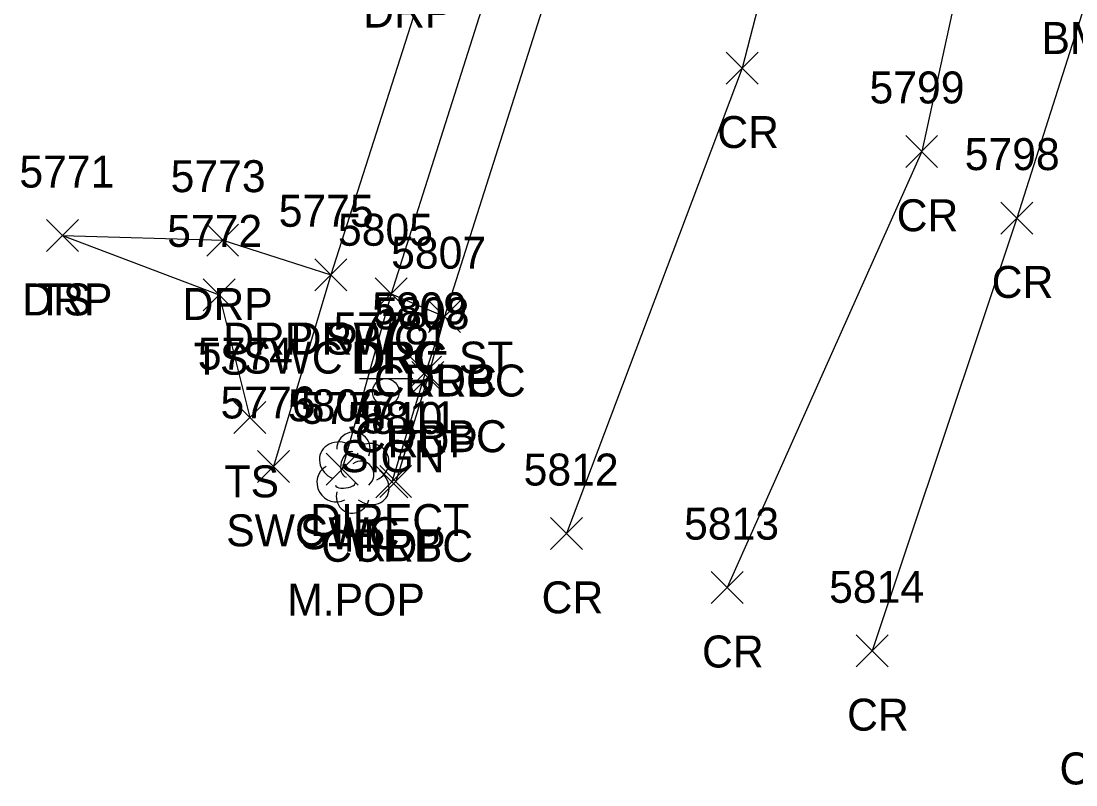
# Model space of a CAD drawing. Extents: x 1462089 to 1464015, y 730534 to 736144.
# Drawn here: x 1462304.3 to 1462370.3, y 730545.4 to 730593.2 of the extents above; entities that cross this region are included whole.
import ezdxf

# ---------------------------------------------------------------- set-up
doc = ezdxf.new("R2010")
doc.units = 0
for name, color, linetype in [('C_C', 7, 'Continuous'), ('L_A', 7, 'Continuous'), ('L_C', 7, 'Continuous'), ('L_I', 7, 'Continuous'), ('L_TIC', 7, 'Continuous'), ('LELB', 7, 'Continuous'), ('LTD', 7, 'Continuous'), ('P_A', 7, 'Continuous'), ('P_I', 7, 'Continuous'), ('P_TIC', 7, 'Continuous'), ('PET', 7, 'Continuous'), ('PRC', 7, 'Continuous'), ('R_A', 7, 'Continuous'), ('R_I', 7, 'Continuous'), ('R_TIC', 7, 'Continuous'), ('RC', 7, 'Continuous'), ('RDP', 7, 'Continuous'), ('RSW', 7, 'Continuous'), ('S_A', 7, 'Continuous'), ('S_C', 7, 'Continuous'), ('S_I', 7, 'Continuous'), ('SSGN', 7, 'Continuous')]:
    doc.layers.add(name, color=color, linetype=linetype)

msp = doc.modelspace()

# ---------------------------------------------------------------- linework, layer by layer
at = {"layer": 'L_TIC'}
for points in [[(1462305.867, 730578.733), (1462307.867, 730580.733)], [(1462307.867, 730578.733), (1462305.867, 730580.733)], [(1462315.69, 730575.023), (1462317.69, 730577.023)], [(1462317.69, 730575.023), (1462315.69, 730577.023)], [(1462317.609, 730567.347), (1462319.609, 730569.347)], [(1462319.609, 730567.347), (1462317.609, 730569.347)]]:
    msp.add_lwpolyline(points, dxfattribs=at)
at = {"layer": 'LELB'}
msp.add_lwpolyline([(1462306.867, 730579.733), (1462316.69, 730576.023), (1462318.609, 730568.347)], dxfattribs=at)
at = {"layer": 'LTD'}
msp.add_line((1462325.05, 730564.948), (1462325.05, 730564.948), dxfattribs=at)
msp.add_line((1462325.05, 730564.948), (1462325.05, 730564.948), dxfattribs=at)
msp.add_arc((1462325.096, 730566.382), 1.047, 335.52715, 180.95627, dxfattribs=at)
for centre, major_axis, ratio, start_param, end_param in [((1462324.258, 730565.615), (1.21, -0.512), 0.895232, 1.570796, 4.712389), ((1462326.091, 730565.532), (-1.141, -0.483), 0.949671, 1.570796, 4.712389), ((1462324.841, 730565.407), (-0.208, -0.792), 0.645439, 3.141593, 6.283185), ((1462325.55, 730564.782), (-0.5, 0.667), 0.989748, 3.141593, 6.283185), ((1462323.967, 730564.24), (0.584, -1.042), 0.959034, 3.141593, 6.283185), ((1462326.05, 730564.115), (-1.09, 0.792), 0.841452, 1.570796, 4.712389), ((1462325.05, 730563.448), (0.265, 1.061), 0.942809, 1.570796, 4.712389), ((1462324.592, 730564.198), (-0.625, -0.083), 0.423636, 0, 3.141593)]:
    msp.add_ellipse(centre, major_axis=major_axis, ratio=ratio, start_param=start_param, end_param=end_param, dxfattribs=at)
at = {"layer": 'P_TIC'}
for points in [[(1462348.446, 730589.208), (1462350.446, 730591.208)], [(1462350.446, 730589.208), (1462348.446, 730591.208)], [(1462359.68, 730584), (1462361.68, 730586)], [(1462361.68, 730584), (1462359.68, 730586)], [(1462365.634, 730579.828), (1462367.634, 730581.828)], [(1462367.634, 730579.828), (1462365.634, 730581.828)], [(1462329.793, 730573.658), (1462331.793, 730575.658)], [(1462331.793, 730573.658), (1462329.793, 730575.658)], [(1462328.749, 730569.858), (1462330.749, 730571.858)], [(1462330.749, 730569.858), (1462328.749, 730571.858)], [(1462326.74, 730563.348), (1462328.74, 730565.348)], [(1462328.74, 730563.348), (1462326.74, 730565.348)], [(1462337.444, 730560.087), (1462339.444, 730562.087)], [(1462339.444, 730560.087), (1462337.444, 730562.087)], [(1462347.492, 730556.7), (1462349.492, 730558.7)], [(1462349.492, 730556.7), (1462347.492, 730558.7)], [(1462356.577, 730552.747), (1462358.577, 730554.747)], [(1462358.577, 730552.747), (1462356.577, 730554.747)]]:
    msp.add_lwpolyline(points, dxfattribs=at)
at = {"layer": 'PET'}
msp.add_lwpolyline([(1462369.308, 730697.926), (1462368.209, 730694.185), (1462362.156, 730675.48), (1462361.372, 730672.287), (1462352.142, 730642.733), (1462339.819, 730603.063), (1462338.492, 730598.895), (1462330.793, 730574.658), (1462329.749, 730570.858), (1462327.74, 730564.348)], dxfattribs=at)
at = {"layer": 'PRC'}
for points in [[(1462502.241, 731140.649), (1462491.591, 731093.412), (1462481.409, 731051.886), (1462466.381, 730998.853), (1462449.742, 730941.326), (1462438.111, 730890.414), (1462425.454, 730844.203), (1462414.378, 730806.637), (1462401.133, 730755.946), (1462392.12, 730727.265), (1462378.758, 730682.128), (1462374.561, 730668.664), (1462358.3, 730624.573), (1462349.446, 730590.208), (1462338.444, 730561.087)], [(1462522.114, 731136.266), (1462509.014, 731086.504), (1462495.843, 731048.676), (1462480.832, 730995.433), (1462460.794, 730938.782), (1462449.007, 730886.807), (1462435.474, 730841.095), (1462424.603, 730802.226), (1462409.981, 730750.745), (1462401.876, 730724.374), (1462388.003, 730678.771), (1462384.493, 730666.354), (1462369.098, 730623.58), (1462360.68, 730585), (1462348.492, 730557.7)], [(1462531.515, 731132.984), (1462517.28, 731085.282), (1462509.353, 731045.029), (1462493.599, 730992.368), (1462476.953, 730933.085), (1462462.375, 730883.835), (1462447.905, 730837.268), (1462435.369, 730797.923), (1462416.948, 730748.336), (1462410.801, 730719.379), (1462396.341, 730673.49), (1462394.762, 730664.922), (1462379.239, 730620.511), (1462379.284, 730620.518), (1462366.634, 730580.828), (1462357.577, 730553.747)]]:
    msp.add_lwpolyline(points, dxfattribs=at)
at = {"layer": 'R_TIC'}
for points in [[(1462305.867, 730578.733), (1462307.867, 730580.733)], [(1462307.867, 730578.733), (1462305.867, 730580.733)], [(1462315.905, 730578.447), (1462317.905, 730580.447)], [(1462317.905, 730578.447), (1462315.905, 730580.447)], [(1462322.672, 730576.282), (1462324.672, 730578.282)], [(1462324.672, 730576.282), (1462322.672, 730578.282)], [(1462322.672, 730576.282), (1462324.672, 730578.282)], [(1462324.672, 730576.282), (1462322.672, 730578.282)], [(1462326.462, 730575.094), (1462328.462, 730577.094)], [(1462328.462, 730575.094), (1462326.462, 730577.094)], [(1462326.462, 730575.094), (1462328.462, 730577.094)], [(1462328.462, 730575.094), (1462326.462, 730577.094)], [(1462329.793, 730573.658), (1462331.793, 730575.658)], [(1462331.793, 730573.658), (1462329.793, 730575.658)], [(1462329.793, 730573.658), (1462331.793, 730575.658)], [(1462331.793, 730573.658), (1462329.793, 730575.658)], [(1462328.606, 730570.173), (1462330.606, 730572.173)], [(1462330.606, 730570.173), (1462328.606, 730572.173)], [(1462319.084, 730564.284), (1462321.084, 730566.284)], [(1462321.084, 730564.284), (1462319.084, 730566.284)], [(1462323.382, 730564.104), (1462325.382, 730566.104)], [(1462325.382, 730564.104), (1462323.382, 730566.104)], [(1462326.499, 730563.316), (1462328.499, 730565.316)], [(1462328.499, 730563.316), (1462326.499, 730565.316)]]:
    msp.add_lwpolyline(points, dxfattribs=at)
at = {"layer": 'RC'}
msp.add_lwpolyline([(1462330.793, 730574.658), (1462329.606, 730571.173), (1462327.499, 730564.316)], dxfattribs=at)
at = {"layer": 'RDP'}
for points in [[(1462306.867, 730579.733), (1462316.905, 730579.447), (1462323.672, 730577.282)], [(1462327.462, 730576.094), (1462330.793, 730574.658)]]:
    msp.add_lwpolyline(points, dxfattribs=at)
at = {"layer": 'RSW'}
for points in [[(1462360.519, 730693.816), (1462356.442, 730681.408), (1462355.857, 730679.16), (1462349.665, 730659.971), (1462348.127, 730654.542), (1462330.678, 730599.137), (1462323.672, 730577.282), (1462320.084, 730565.284)], [(1462348.724, 730643.964), (1462334.507, 730598.298), (1462327.462, 730576.094), (1462324.382, 730565.104)]]:
    msp.add_lwpolyline(points, dxfattribs=at)
at = {"layer": 'SSGN'}
for p, q in [((1462325.479, 730570.777), (1462328.813, 730570.777)), ((1462327.126, 730569.943), (1462327.126, 730569.943))]:
    msp.add_line(p, q, dxfattribs=at)
msp.add_circle((1462327.126, 730569.943), 0.833, dxfattribs=at)

# ---------------------------------------------------------------- texts
at = {"layer": 'C_C'}
msp.add_text('BM28 RRSIR M.LOC ELEV:323.29', height=2, dxfattribs=at).set_placement((1462368.181, 730591.095))
at = {"layer": 'L_A'}
for s, p in [('TS', (1462305.277, 730574.733)), ('TS', (1462315.099, 730571.023)), ('TS', (1462317.018, 730563.347)), ('H', (1462324.483, 730559.948))]:
    msp.add_text(s, height=2, dxfattribs=at).set_placement(p)
at = {"layer": 'L_C'}
msp.add_text('M.POP', height=2, dxfattribs=at).set_placement((1462320.947, 730555.948))
at = {"layer": 'L_I'}
for s, p in [('5771', (1462304.174, 730582.733)), ('5772', (1462313.43, 730579.023)), ('5774', (1462315.349, 730571.347)), ('5777', (1462321.79, 730567.948))]:
    msp.add_text(s, height=2, dxfattribs=at).set_placement(p)
at = {"layer": 'P_A'}
for s, p in [('CR', (1462347.879, 730585.208)), ('CR', (1462359.113, 730580)), ('CR', (1462365.067, 730575.828)), ('RDP', (1462328.281, 730569.658)), ('RDP', (1462327.237, 730565.858)), ('RDP', (1462325.228, 730559.348)), ('CR', (1462336.878, 730556.087)), ('CR', (1462346.925, 730552.7)), ('CR', (1462356.011, 730548.747))]:
    msp.add_text(s, height=2, dxfattribs=at).set_placement(p)
at = {"layer": 'P_I'}
for s, p in [('5799', (1462357.412, 730588)), ('5798', (1462363.374, 730583.828)), ('5807', (1462327.454, 730577.658)), ('5808', (1462326.411, 730573.858)), ('5811', (1462325.614, 730567.348)), ('5812', (1462335.752, 730564.087)), ('5813', (1462345.799, 730560.7)), ('5814', (1462354.885, 730556.747))]:
    msp.add_text(s, height=2, dxfattribs=at).set_placement(p)
at = {"layer": 'R_A'}
for s, p in [('DRP', (1462325.71, 730592.75)), ('DRP', (1462304.355, 730574.733)), ('DRP', (1462314.393, 730574.447)), ('DRP SWC1', (1462316.932, 730572.282)), ('DRP', (1462321.16, 730572.282)), ('SWC DRC ST', (1462318.179, 730571.094)), ('DRC', (1462324.95, 730571.094)), ('CURBC', (1462326.375, 730569.658)), ('DRC', (1462328.281, 730569.658)), ('CURBC', (1462325.189, 730566.173)), ('SWC1', (1462317.124, 730560.284)), ('SWC', (1462321.744, 730560.104)), ('CURBC', (1462323.082, 730559.316)), ('CURBC', (1462369.314, 730545.381))]:
    msp.add_text(s, height=2, dxfattribs=at).set_placement(p)
at = {"layer": 'R_I'}
for s, p in [('5771', (1462304.174, 730582.733)), ('5773', (1462313.645, 730582.447)), ('5775', (1462320.413, 730580.282)), ('5775', (1462320.413, 730580.282)), ('5805', (1462324.124, 730579.094)), ('5805', (1462324.124, 730579.094)), ('5807', (1462327.454, 730577.658)), ('5807', (1462327.454, 730577.658)), ('5809', (1462326.26, 730574.173)), ('5776', (1462316.77, 730568.284)), ('5806', (1462320.988, 730568.104)), ('5810', (1462324.72, 730567.316))]:
    msp.add_text(s, height=2, dxfattribs=at).set_placement(p)
at = {"layer": 'S_A'}
msp.add_text('SIGN', height=2, dxfattribs=at).set_placement((1462324.264, 730564.923))
at = {"layer": 'S_C'}
msp.add_text('DIRECT', height=2, dxfattribs=at).set_placement((1462322.39, 730560.923))
at = {"layer": 'S_I'}
msp.add_text('5778', height=2, dxfattribs=at).set_placement((1462323.847, 730572.923))

doc.saveas('drawing.dxf')
